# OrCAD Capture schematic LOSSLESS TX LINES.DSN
size A4
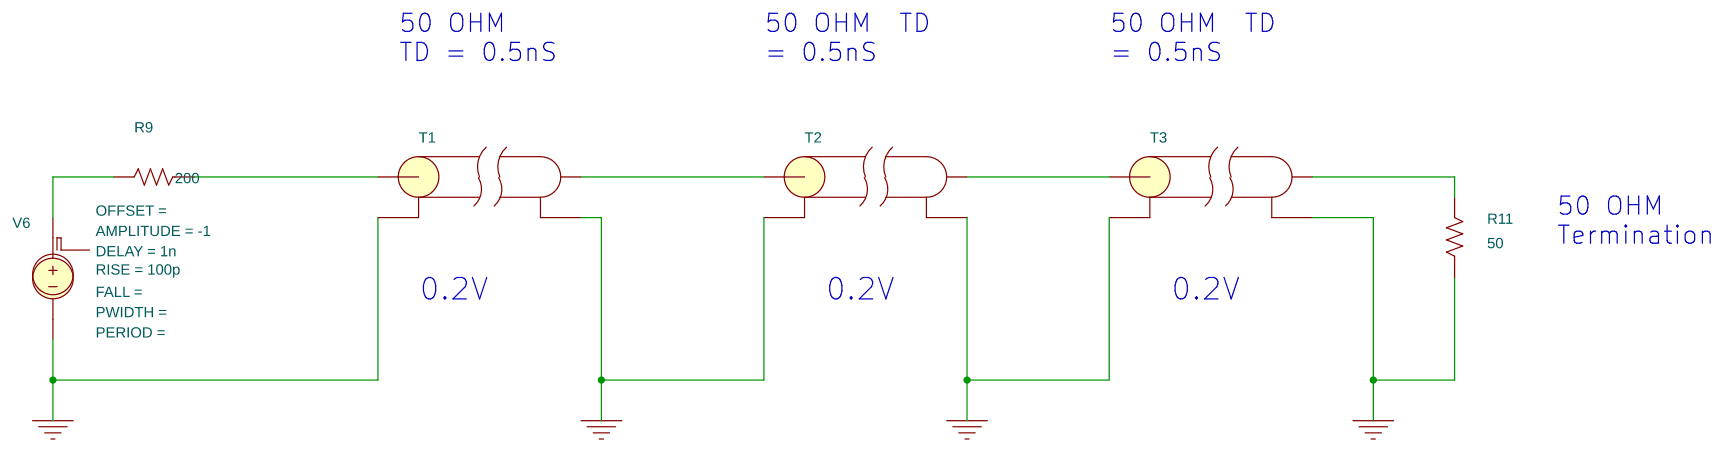
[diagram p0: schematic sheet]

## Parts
R9  200  [RC05]
R11  50  [RC05]
T1  T
T2  T
T3  T
V6  ?DC|DC @DC| ?AC|AC @AC|\n+PULSE @OFFSET @AMPLITUDE+@OFFSET ?DELAY/@DELAY/~DELAY/0/ #RISE/@RISE/ #FALL/@FALL/ #PWIDTH/@PWIDTH/ #PERIOD/@PERIOD/

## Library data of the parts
R9 R11 = R
T1-T3 = T: TD: 0.5n; Z0: 50
V6 = V_PULSE: AMPLITUDE: -1; DELAY: 1n; RISE: 100p

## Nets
0: R11.1 T1.2(A-) T1.4(B-) T2.2(A-) T2.4(B-) T3.2(A-) T3.4(B-) V6.1(NVS)
N17505: R9.2 V6.2(PVS)
N17515: R9.1 T1.1(A+)
N18075: T1.3(B+) T2.1(A+)
N18870: R11.2 T3.3(B+)
N19026: T2.3(B+) T3.1(A+)

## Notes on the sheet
- 50 OHM
  TD = 0.5nS
- 50 OHM  TD
  = 0.5nS
- 50 OHM  TD
  = 0.5nS
- 50 OHM
  Termination
- 0.2V
- 0.2V
- 0.2V
